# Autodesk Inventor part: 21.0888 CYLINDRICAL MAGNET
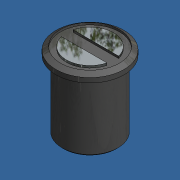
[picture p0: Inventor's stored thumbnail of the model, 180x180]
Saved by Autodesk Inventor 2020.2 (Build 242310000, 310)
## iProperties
Part Number: 21.0888 CYLINDRICAL MAGNET
Material: Steel, Mild
Document SubType Name: Modeling
Designer: amoles
Appearance: Semi-Polished
Mass: 51.3398 g
Surface Area: 21.5209 cm^2
Volume: 6.54011 cm^3
Density: 7.85 g/cm^3
Author: amoles
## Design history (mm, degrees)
feature "Base1"
sketch "Sketch1"
  geometry: C1 r 1.9 at (0, 0) reference; C2 r 10 at (0, 0) reference
extrude "Extrusion1" cut sketch "Sketch1" distance "d0" = 3.5; taper "d1" = 0 deg
sketch "Sketch3"
  geometry: C1 r 9.5 at (0, 0) reference; C2 r 7.625 at (0, 0)
  constraints: 1 centre point, 1 coincident
  dimensions: "d5" = 15.25 diameter of C2
extrude "Extrusion3" cut sketch "Sketch3" distance "d6" = 0.7; taper "d7" = 0 deg
sketch "Sketch4"
  geometry: L1 (-11.248, 1.9)-(11.147, 1.9); L2 (11.147, 1.9)-(11.147, -1.9); L3 (11.147, -1.9)-(-11.248, -1.9); L4 (-11.248, -1.9)-(-11.248, 1.9); C1 r 7.625 at (0, 0) reference; 5 further points
  constraints: 8 end point, 2 parallel, 1 horizontal, 1 horizontal alignment, 1 midpoint, 1 perpendicular
  dimensions: "d8" = 3.8 distance of L1.end L2.end
extrude "Extrusion4" cut sketch "Sketch4" distance "d9" = 0.7; taper "d10" = 0 deg
body "Solid1"
